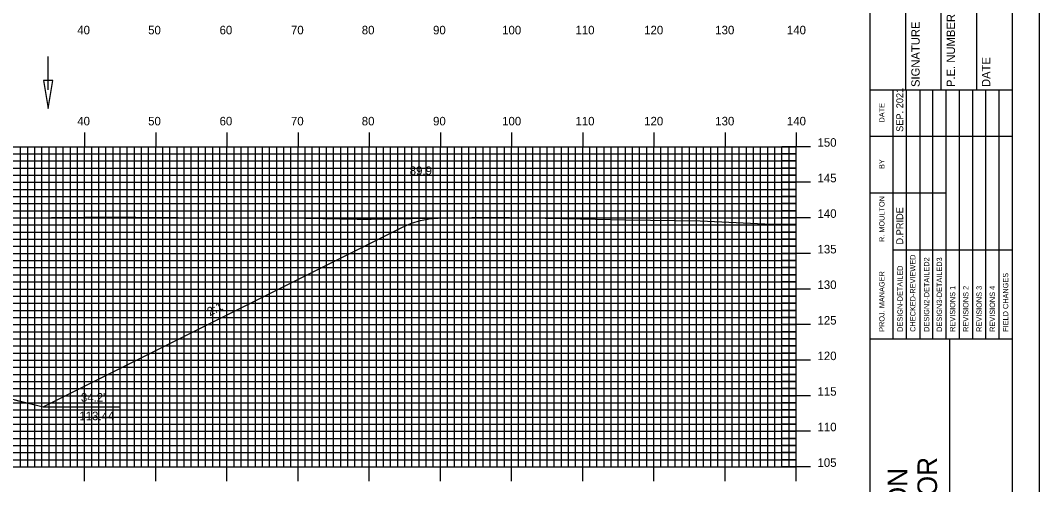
# Model space of a CAD drawing. Extents: x 1768874 to 1769217, y 442591 to 442811.
# Drawn here: x 1769071 to 1769214.2, y 442666.2 to 442731.4 of the extents above; entities that cross this region are included whole.
import ezdxf

# ---------------------------------------------------------------- set-up
doc = ezdxf.new("R2010")
doc.units = 0
for name, color, linetype in [('ANNOTATION', 7, 'Continuous'), ('BORDER', 7, 'Continuous'), ('D_Drainage_Ditch_Line', 7, 'Continuous'), ('D_Roadway_Centerline', 7, 'Continuous'), ('D_Roadway_SlopeLines', 7, 'Continuous'), ('D_Text_Standard', 7, 'Continuous'), ('H_V ANNOTATION', 7, 'Continuous'), ('MAJOR', 7, 'Continuous'), ('MINOR', 7, 'Continuous'), ('PDRAIN', 7, 'Continuous'), ('PLOT BOUNDARY', 7, 'Continuous'), ('S_Roadway_Centerline', 7, 'Continuous')]:
    doc.layers.add(name, color=color, linetype=linetype)

msp = doc.modelspace()

# ---------------------------------------------------------------- linework, layer by layer
at = {"layer": 'BORDER'}
for p, q in [((1769190.39, 442596.67), (1769190.39, 442806.67)), ((1769195.39, 442721.67), (1769195.39, 442738.97)), ((1769200.39, 442721.67), (1769200.39, 442738.97)), ((1769205.39, 442721.67), (1769205.39, 442738.97)), ((1769190.39, 442721.67), (1769210.39, 442721.67)), ((1769190.39, 442686.67), (1769210.39, 442686.67)), ((1769201.57, 442616.67), (1769201.57, 442686.67))]:
    msp.add_line(p, q, dxfattribs=at)
msp.add_lwpolyline([(1768890.39, 442596.67), (1769210.39, 442596.67), (1769210.39, 442806.67), (1768890.39, 442806.67)], close=True, dxfattribs=at)
for points in [[(1769193.62, 442715.17), (1769193.62, 442721.67)], [(1769195.48, 442686.68), (1769195.48, 442721.67)], [(1769197.35, 442721.67), (1769197.35, 442686.68)], [(1769199.21, 442686.68), (1769199.21, 442721.67)], [(1769201.07, 442686.68), (1769201.07, 442721.67)], [(1769202.94, 442686.68), (1769202.94, 442721.67)], [(1769204.8, 442686.68), (1769204.8, 442721.67)], [(1769206.66, 442686.68), (1769206.66, 442721.67)], [(1769208.53, 442686.68), (1769208.53, 442721.67)], [(1769193.62, 442686.68), (1769193.62, 442720.26)], [(1769190.39, 442715.17), (1769210.39, 442715.17)], [(1769190.39, 442707.17), (1769193.62, 442707.17)], [(1769193.62, 442707.17), (1769201.07, 442707.17)], [(1769193.62, 442699.17), (1769210.39, 442699.17)]]:
    msp.add_lwpolyline(points, dxfattribs=at)
at = {"layer": 'D_Drainage_Ditch_Line'}
msp.add_line((1769074.85, 442721.66), (1769074.85, 442726.36), dxfattribs=at)
msp.add_lwpolyline([(1769075.51, 442722.97), (1769074.2, 442722.97), (1769074.85, 442719.03)], close=True, dxfattribs=at)
at = {"layer": 'D_Roadway_Centerline'}
msp.add_lwpolyline([(1769070.16, 442678.1), (1769074.16, 442677.1), (1769089.73, 442684.88), (1769124.68, 442702.36), (1769125.93, 442702.91), (1769127.18, 442703.31), (1769128.11, 442703.49), (1769128.43, 442703.55), (1769129.68, 442703.65)], dxfattribs=at)
at = {"layer": 'D_Roadway_SlopeLines'}
for points in [[(1769074.16, 442677.1), (1769124.68, 442702.36), (1769125.93, 442702.91), (1769127.18, 442703.31), (1769128.43, 442703.55), (1769129.68, 442703.65)], [(1769059.99, 442680.65), (1769074.16, 442677.1)]]:
    msp.add_lwpolyline(points, dxfattribs=at)
at = {"layer": 'MAJOR'}
for p, q in [((1769079.99, 442715.67), (1769079.99, 442713.67)), ((1769089.99, 442715.67), (1769089.99, 442713.67)), ((1769099.99, 442715.67), (1769099.99, 442713.67)), ((1769109.99, 442715.67), (1769109.99, 442713.67)), ((1769119.99, 442715.67), (1769119.99, 442713.67)), ((1769129.99, 442715.67), (1769129.99, 442713.67)), ((1769139.99, 442715.67), (1769139.99, 442713.67)), ((1769149.99, 442715.67), (1769149.99, 442713.67)), ((1769159.99, 442715.67), (1769159.99, 442713.67)), ((1769169.99, 442715.67), (1769169.99, 442713.67)), ((1769179.99, 442715.67), (1769179.99, 442713.67)), ((1768899.99, 442713.67), (1769179.99, 442713.67)), ((1768899.99, 442713.67), (1769179.99, 442713.67)), ((1769079.99, 442668.67), (1769079.99, 442713.67)), ((1769089.99, 442668.67), (1769089.99, 442713.67)), ((1769099.99, 442668.67), (1769099.99, 442713.67)), ((1769109.99, 442668.67), (1769109.99, 442713.67)), ((1769119.99, 442668.67), (1769119.99, 442713.67)), ((1769129.99, 442668.67), (1769129.99, 442713.67)), ((1769139.99, 442668.67), (1769139.99, 442713.67)), ((1769149.99, 442668.67), (1769149.99, 442713.67)), ((1769159.99, 442668.67), (1769159.99, 442713.67)), ((1769169.99, 442668.67), (1769169.99, 442713.67)), ((1769181.99, 442713.67), (1769177.98, 442713.67)), ((1769179.99, 442668.67), (1769179.99, 442713.67)), ((1769179.99, 442668.67), (1769179.99, 442713.67)), ((1768899.99, 442708.67), (1769179.99, 442708.67)), ((1769181.99, 442708.67), (1769177.98, 442708.67)), ((1768899.99, 442703.67), (1769179.99, 442703.67)), ((1769181.99, 442703.67), (1769177.98, 442703.67)), ((1768899.99, 442698.67), (1769179.99, 442698.67)), ((1769181.99, 442698.67), (1769177.98, 442698.67)), ((1768899.99, 442693.67), (1769179.99, 442693.67)), ((1769181.99, 442693.67), (1769177.98, 442693.67)), ((1768899.99, 442688.67), (1769179.99, 442688.67)), ((1769181.99, 442688.67), (1769177.98, 442688.67)), ((1768899.99, 442683.67), (1769179.99, 442683.67)), ((1769181.99, 442683.67), (1769177.98, 442683.67)), ((1768899.99, 442678.67), (1769179.99, 442678.67)), ((1769181.99, 442678.67), (1769177.98, 442678.67)), ((1768899.99, 442673.67), (1769179.99, 442673.67)), ((1769181.99, 442673.67), (1769177.98, 442673.67)), ((1768899.99, 442668.67), (1769179.99, 442668.67)), ((1768899.99, 442668.67), (1769179.99, 442668.67)), ((1769079.99, 442666.66), (1769079.99, 442668.67)), ((1769089.99, 442666.66), (1769089.99, 442668.67)), ((1769099.99, 442666.66), (1769099.99, 442668.67)), ((1769109.99, 442666.66), (1769109.99, 442668.67)), ((1769119.99, 442666.66), (1769119.99, 442668.67)), ((1769129.99, 442666.66), (1769129.99, 442668.67)), ((1769139.99, 442666.66), (1769139.99, 442668.67)), ((1769149.99, 442666.66), (1769149.99, 442668.67)), ((1769159.99, 442666.66), (1769159.99, 442668.67)), ((1769169.99, 442666.66), (1769169.99, 442668.67)), ((1769181.99, 442668.67), (1769177.98, 442668.67)), ((1769179.99, 442666.66), (1769179.99, 442668.67))]:
    msp.add_line(p, q, dxfattribs=at)
at = {"layer": 'MINOR'}
for p, q in [((1768899.99, 442712.67), (1769179.99, 442712.67)), ((1769070.99, 442668.67), (1769070.99, 442713.67)), ((1769071.99, 442668.67), (1769071.99, 442713.67)), ((1769072.99, 442668.67), (1769072.99, 442713.67)), ((1769073.99, 442668.67), (1769073.99, 442713.67)), ((1769074.99, 442668.67), (1769074.99, 442713.67)), ((1769075.99, 442668.67), (1769075.99, 442713.67)), ((1769076.99, 442668.67), (1769076.99, 442713.67)), ((1769077.99, 442668.67), (1769077.99, 442713.67)), ((1769078.99, 442668.67), (1769078.99, 442713.67)), ((1769080.99, 442668.67), (1769080.99, 442713.67)), ((1769081.99, 442668.67), (1769081.99, 442713.67)), ((1769082.99, 442668.67), (1769082.99, 442713.67)), ((1769083.99, 442668.67), (1769083.99, 442713.67)), ((1769084.99, 442668.67), (1769084.99, 442713.67)), ((1769085.99, 442668.67), (1769085.99, 442713.67)), ((1769086.99, 442668.67), (1769086.99, 442713.67)), ((1769087.99, 442668.67), (1769087.99, 442713.67)), ((1769088.99, 442668.67), (1769088.99, 442713.67)), ((1769090.99, 442668.67), (1769090.99, 442713.67)), ((1769091.99, 442668.67), (1769091.99, 442713.67)), ((1769092.99, 442668.67), (1769092.99, 442713.67)), ((1769093.99, 442668.67), (1769093.99, 442713.67)), ((1769094.99, 442668.67), (1769094.99, 442713.67)), ((1769095.99, 442668.67), (1769095.99, 442713.67)), ((1769096.99, 442668.67), (1769096.99, 442713.67)), ((1769097.99, 442668.67), (1769097.99, 442713.67)), ((1769098.99, 442668.67), (1769098.99, 442713.67)), ((1769100.99, 442668.67), (1769100.99, 442713.67)), ((1769101.99, 442668.67), (1769101.99, 442713.67)), ((1769102.99, 442668.67), (1769102.99, 442713.67)), ((1769103.99, 442668.67), (1769103.99, 442713.67)), ((1769104.99, 442668.67), (1769104.99, 442713.67)), ((1769105.99, 442668.67), (1769105.99, 442713.67)), ((1769106.99, 442668.67), (1769106.99, 442713.67)), ((1769107.99, 442668.67), (1769107.99, 442713.67)), ((1769108.99, 442668.67), (1769108.99, 442713.67)), ((1769110.99, 442668.67), (1769110.99, 442713.67)), ((1769111.99, 442668.67), (1769111.99, 442713.67)), ((1769112.99, 442668.67), (1769112.99, 442713.67)), ((1769113.99, 442668.67), (1769113.99, 442713.67)), ((1769114.99, 442668.67), (1769114.99, 442713.67)), ((1769115.99, 442668.67), (1769115.99, 442713.67)), ((1769116.99, 442668.67), (1769116.99, 442713.67)), ((1769117.99, 442668.67), (1769117.99, 442713.67)), ((1769118.99, 442668.67), (1769118.99, 442713.67)), ((1769120.99, 442668.67), (1769120.99, 442713.67)), ((1769121.99, 442668.67), (1769121.99, 442713.67)), ((1769122.99, 442668.67), (1769122.99, 442713.67)), ((1769123.99, 442668.67), (1769123.99, 442713.67)), ((1769124.99, 442668.67), (1769124.99, 442713.67)), ((1769125.99, 442668.67), (1769125.99, 442713.67)), ((1769126.99, 442668.67), (1769126.99, 442713.67)), ((1769127.99, 442668.67), (1769127.99, 442713.67)), ((1769128.99, 442668.67), (1769128.99, 442713.67)), ((1769130.99, 442668.67), (1769130.99, 442713.67)), ((1769131.99, 442668.67), (1769131.99, 442713.67)), ((1769132.99, 442668.67), (1769132.99, 442713.67)), ((1769133.99, 442668.67), (1769133.99, 442713.67)), ((1769134.99, 442668.67), (1769134.99, 442713.67)), ((1769135.99, 442668.67), (1769135.99, 442713.67)), ((1769136.99, 442668.67), (1769136.99, 442713.67)), ((1769137.99, 442668.67), (1769137.99, 442713.67)), ((1769138.99, 442668.67), (1769138.99, 442713.67)), ((1769140.99, 442668.67), (1769140.99, 442713.67)), ((1769141.99, 442668.67), (1769141.99, 442713.67)), ((1769142.99, 442668.67), (1769142.99, 442713.67)), ((1769143.99, 442668.67), (1769143.99, 442713.67)), ((1769144.99, 442668.67), (1769144.99, 442713.67)), ((1769145.99, 442668.67), (1769145.99, 442713.67)), ((1769146.99, 442668.67), (1769146.99, 442713.67)), ((1769147.99, 442668.67), (1769147.99, 442713.67)), ((1769148.99, 442668.67), (1769148.99, 442713.67)), ((1769150.99, 442668.67), (1769150.99, 442713.67)), ((1769151.99, 442668.67), (1769151.99, 442713.67)), ((1769152.99, 442668.67), (1769152.99, 442713.67)), ((1769153.99, 442668.67), (1769153.99, 442713.67)), ((1769154.99, 442668.67), (1769154.99, 442713.67)), ((1769155.99, 442668.67), (1769155.99, 442713.67)), ((1769156.99, 442668.67), (1769156.99, 442713.67)), ((1769157.99, 442668.67), (1769157.99, 442713.67)), ((1769158.99, 442668.67), (1769158.99, 442713.67)), ((1769160.99, 442668.67), (1769160.99, 442713.67)), ((1769161.99, 442668.67), (1769161.99, 442713.67)), ((1769162.99, 442668.67), (1769162.99, 442713.67)), ((1769163.99, 442668.67), (1769163.99, 442713.67)), ((1769164.99, 442668.67), (1769164.99, 442713.67)), ((1769165.99, 442668.67), (1769165.99, 442713.67)), ((1769166.99, 442668.67), (1769166.99, 442713.67)), ((1769167.99, 442668.67), (1769167.99, 442713.67)), ((1769168.99, 442668.67), (1769168.99, 442713.67)), ((1769170.99, 442668.67), (1769170.99, 442713.67)), ((1769171.99, 442668.67), (1769171.99, 442713.67)), ((1769172.99, 442668.67), (1769172.99, 442713.67)), ((1769173.99, 442668.67), (1769173.99, 442713.67)), ((1769174.99, 442668.67), (1769174.99, 442713.67)), ((1769175.99, 442668.67), (1769175.99, 442713.67)), ((1769176.99, 442668.67), (1769176.99, 442713.67)), ((1769179.99, 442712.67), (1769177.98, 442712.67)), ((1769177.99, 442668.67), (1769177.99, 442713.67)), ((1769178.99, 442668.67), (1769178.99, 442713.67)), ((1768899.99, 442711.67), (1769179.99, 442711.67)), ((1769179.99, 442711.67), (1769177.98, 442711.67)), ((1768899.99, 442710.67), (1769179.99, 442710.67)), ((1768899.99, 442709.67), (1769179.99, 442709.67)), ((1769179.99, 442710.67), (1769177.98, 442710.67)), ((1769179.99, 442709.67), (1769177.98, 442709.67)), ((1768899.99, 442707.67), (1769179.99, 442707.67)), ((1769179.99, 442707.67), (1769177.98, 442707.67)), ((1768899.99, 442706.67), (1769179.99, 442706.67)), ((1768899.99, 442705.67), (1769179.99, 442705.67)), ((1769179.99, 442706.67), (1769177.98, 442706.67)), ((1769179.99, 442705.67), (1769177.98, 442705.67)), ((1768899.99, 442704.67), (1769179.99, 442704.67)), ((1769179.99, 442704.67), (1769177.98, 442704.67)), ((1768899.99, 442702.67), (1769179.99, 442702.67)), ((1769179.99, 442702.67), (1769177.98, 442702.67)), ((1768899.99, 442701.67), (1769179.99, 442701.67)), ((1769179.99, 442701.67), (1769177.98, 442701.67)), ((1768899.99, 442700.67), (1769179.99, 442700.67)), ((1768899.99, 442699.67), (1769179.99, 442699.67)), ((1769179.99, 442700.67), (1769177.98, 442700.67)), ((1769179.99, 442699.67), (1769177.98, 442699.67)), ((1768899.99, 442697.67), (1769179.99, 442697.67)), ((1768899.99, 442696.67), (1769179.99, 442696.67)), ((1769179.99, 442697.67), (1769177.98, 442697.67)), ((1769179.99, 442696.67), (1769177.98, 442696.67)), ((1768899.99, 442695.67), (1769179.99, 442695.67)), ((1769179.99, 442695.67), (1769177.98, 442695.67)), ((1768899.99, 442694.67), (1769179.99, 442694.67)), ((1769179.99, 442694.67), (1769177.98, 442694.67)), ((1768899.99, 442692.67), (1769179.99, 442692.67)), ((1769179.99, 442692.67), (1769177.98, 442692.67)), ((1768899.99, 442691.67), (1769179.99, 442691.67)), ((1769179.99, 442691.67), (1769177.98, 442691.67)), ((1768899.99, 442690.67), (1769179.99, 442690.67)), ((1768899.99, 442689.67), (1769179.99, 442689.67)), ((1769179.99, 442690.67), (1769177.98, 442690.67)), ((1769179.99, 442689.67), (1769177.98, 442689.67)), ((1768899.99, 442687.67), (1769179.99, 442687.67)), ((1768899.99, 442686.67), (1769179.99, 442686.67)), ((1769179.99, 442687.67), (1769177.98, 442687.67)), ((1769179.99, 442686.67), (1769177.98, 442686.67)), ((1768899.99, 442685.67), (1769179.99, 442685.67)), ((1769179.99, 442685.67), (1769177.98, 442685.67)), ((1768899.99, 442684.67), (1769179.99, 442684.67)), ((1769179.99, 442684.67), (1769177.98, 442684.67)), ((1768899.99, 442682.67), (1769179.99, 442682.67)), ((1769179.99, 442682.67), (1769177.98, 442682.67)), ((1768899.99, 442681.67), (1769179.99, 442681.67)), ((1769179.99, 442681.67), (1769177.98, 442681.67)), ((1768899.99, 442680.67), (1769179.99, 442680.67)), ((1768899.99, 442679.67), (1769179.99, 442679.67)), ((1769179.99, 442680.67), (1769177.98, 442680.67)), ((1769179.99, 442679.67), (1769177.98, 442679.67)), ((1768899.99, 442677.67), (1769179.99, 442677.67)), ((1768899.99, 442676.67), (1769179.99, 442676.67)), ((1769179.99, 442677.67), (1769177.98, 442677.67)), ((1769179.99, 442676.67), (1769177.98, 442676.67)), ((1768899.99, 442675.67), (1769179.99, 442675.67)), ((1769179.99, 442675.67), (1769177.98, 442675.67)), ((1768899.99, 442674.67), (1769179.99, 442674.67)), ((1769179.99, 442674.67), (1769177.98, 442674.67)), ((1768899.99, 442672.67), (1769179.99, 442672.67)), ((1769179.99, 442672.67), (1769177.98, 442672.67)), ((1768899.99, 442671.67), (1769179.99, 442671.67)), ((1769179.99, 442671.67), (1769177.98, 442671.67)), ((1768899.99, 442670.67), (1769179.99, 442670.67)), ((1768899.99, 442669.67), (1769179.99, 442669.67)), ((1769179.99, 442670.67), (1769177.98, 442670.67)), ((1769179.99, 442669.67), (1769177.98, 442669.67))]:
    msp.add_line(p, q, dxfattribs=at)
at = {"layer": 'PDRAIN'}
msp.add_line((1769074.16, 442677.1), (1769084.93, 442677.1), dxfattribs=at)
at = {"layer": 'PLOT BOUNDARY'}
msp.add_lwpolyline([(1768874.2, 442590.55), (1769214.2, 442590.55), (1769214.2, 442810.55), (1768874.2, 442810.55)], close=True, dxfattribs=at)
at = {"layer": 'S_Roadway_Centerline'}
msp.add_lwpolyline([(1769070.74, 442703.68), (1769079.89, 442703.75), (1769082.57, 442703.79), (1769087.17, 442703.78), (1769099.15, 442703.68), (1769106.22, 442703.73), (1769118.28, 442703.51), (1769120.28, 442703.51), (1769137.21, 442703.76), (1769149.69, 442703.52), (1769156, 442703.41), (1769166.51, 442703.27), (1769175.57, 442702.82), (1769179.99, 442702.77)], dxfattribs=at)

# ---------------------------------------------------------------- texts
at = {"layer": 'ANNOTATION'}
msp.add_text('2:1', height=1.2, rotation=26.5652, dxfattribs=at).set_placement((1769097.57, 442689.84))
for s, p in [("34.2'", (1769079.47, 442677.83)), ('113.44', (1769079.25, 442675.23))]:
    msp.add_text(s, height=1.2, dxfattribs=at).set_placement(p)
at = {"layer": 'BORDER'}
for s, height, p in [('SIGNATURE', 1.181, (1769197.35, 442722.06)), ('P.E. NUMBER', 1.1811, (1769202.31, 442722.06)), ('DATE', 1.181, (1769207.27, 442722.06)), ('SEP. 2021', 0.969, (1769195.03, 442715.76)), ('DATE', 0.743, (1769192.4, 442717.08)), ('BY', 0.743, (1769192.4, 442710.54)), ('R. MOULTON', 0.745, (1769192.4, 442700.28)), ('D.PRIDE', 0.969, (1769195.03, 442699.92)), ('CHECKED-REVIEWED', 0.7455, (1769196.75, 442687.65)), ('DESIGN2-DETAILED2', 0.7455, (1769198.69, 442687.65)), ('DESIGN3-DETAILED3', 0.7455, (1769200.48, 442687.65)), ('PROJ. MANAGER', 0.7455, (1769192.4, 442687.65)), ('DESIGN-DETAILED', 0.7455, (1769194.96, 442687.65)), ('FIELD CHANGES', 0.7455, (1769209.79, 442687.65)), ('REVISIONS 1', 0.7455, (1769202.34, 442687.65)), ('REVISIONS 2', 0.7455, (1769204.2, 442687.65)), ('REVISIONS 3', 0.7455, (1769206.07, 442687.65)), ('REVISIONS 4', 0.7455, (1769207.93, 442687.65)), ('1-395/ROUTE 9 CONNECTOR', 2.7557, (1769199.79, 442618.87)), ('BREWER TO EDDINGTON', 2.7557, (1769195.61, 442623.07))]:
    msp.add_text(s, height=height, rotation=90, dxfattribs=at).set_placement(p)
at = {"layer": 'D_Text_Standard'}
msp.add_text("89.9'", height=1.2, dxfattribs=at).set_placement((1769125.68, 442709.7))
at = {"layer": 'H_V ANNOTATION'}
for s, p in [('40', (1769078.96, 442729.47)), ('50', (1769088.92, 442729.47)), ('60', (1769098.96, 442729.47)), ('70', (1769108.99, 442729.47)), ('80', (1769118.94, 442729.47)), ('90', (1769128.96, 442729.47)), ('100', (1769138.67, 442729.47)), ('110', (1769148.97, 442729.47)), ('120', (1769158.63, 442729.47)), ('130', (1769168.62, 442729.47)), ('140', (1769178.69, 442729.47)), ('40', (1769078.96, 442716.67)), ('50', (1769088.92, 442716.67)), ('60', (1769098.96, 442716.67)), ('70', (1769108.99, 442716.67)), ('80', (1769118.94, 442716.67)), ('90', (1769128.96, 442716.67)), ('100', (1769138.67, 442716.67)), ('110', (1769148.97, 442716.67)), ('120', (1769158.63, 442716.67)), ('130', (1769168.62, 442716.67)), ('140', (1769178.69, 442716.67)), ('150', (1769182.99, 442713.67)), ('145', (1769182.99, 442708.67)), ('140', (1769182.99, 442703.67)), ('135', (1769182.99, 442698.67)), ('130', (1769182.99, 442693.67)), ('125', (1769182.99, 442688.67)), ('120', (1769182.99, 442683.67)), ('115', (1769182.99, 442678.67)), ('110', (1769182.99, 442673.67)), ('105', (1769182.99, 442668.67))]:
    msp.add_text(s, height=1.2, dxfattribs=at).set_placement(p)

doc.saveas('drawing.dxf')
